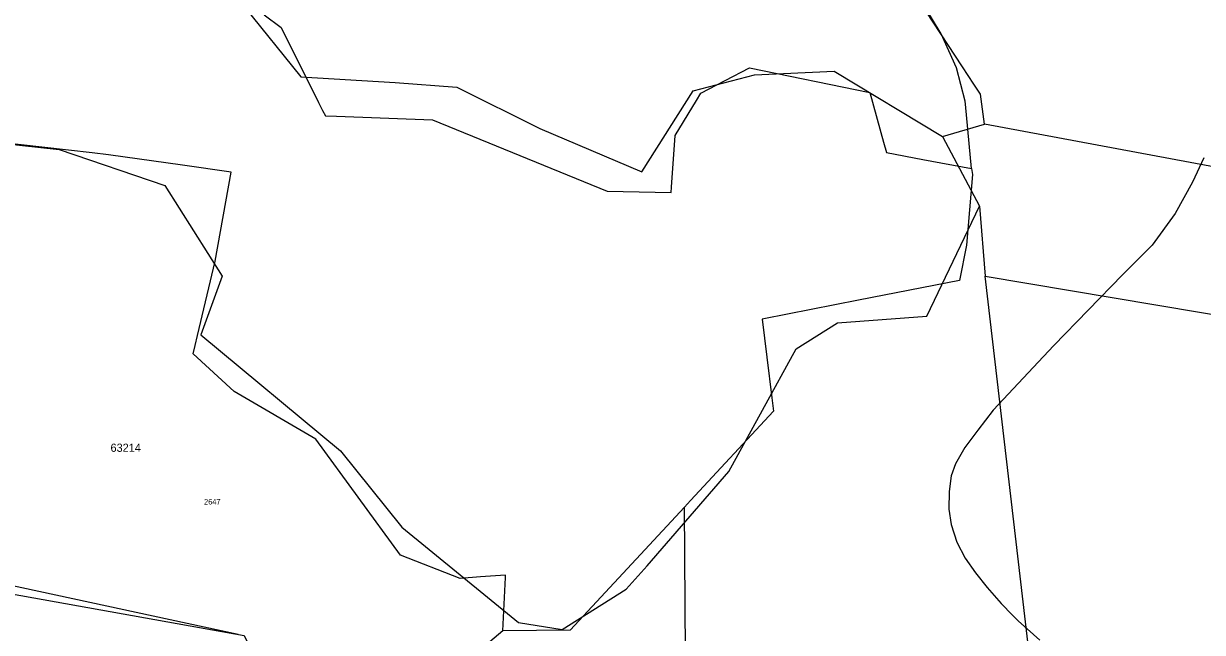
# Model space of a CAD drawing. Extents: x -546762 to -540209, y -1046851 to -1035694.
# Drawn here: x -542107.3 to -541745.8, y -1039679.2 to -1039492.4 of the extents above; entities that cross this region are included whole.
import ezdxf

# ---------------------------------------------------------------- set-up
doc = ezdxf.new("R2010")
doc.units = 0
for name, color, linetype in [('Vrstva 1', 7, 'Continuous'), ('Vrstva 18', 7, 'Continuous'), ('Vrstva 52', 7, 'Continuous'), ('Vrstva 53', 7, 'Continuous')]:
    doc.layers.add(name, color=color, linetype=linetype)

msp = doc.modelspace()

# ---------------------------------------------------------------- linework, layer by layer
at = {"layer": 'Vrstva 1'}
for points in [[(-542039.73, -1039487.11), (-542022.22, -1039508.76)], [(-541819.39, -1039505.7), (-541832.69, -1039485.45)], [(-541815.93, -1039510.98), (-541819.39, -1039505.7)], [(-542022.22, -1039508.76), (-541993.31, -1039510.56)], [(-541901.93, -1039513.05), (-541883.2, -1039508.2)], [(-541883.2, -1039508.2), (-541858.7, -1039506.99)], [(-541858.7, -1039506.99), (-541825.51, -1039527.09)], [(-541993.31, -1039510.56), (-541974.47, -1039511.93)], [(-541974.47, -1039511.93), (-541948.94, -1039524.67)], [(-541917.73, -1039537.91), (-541901.93, -1039513.05)], [(-541813.86, -1039514.13), (-541815.93, -1039510.98)], [(-541812.67, -1039523.33), (-541813.86, -1039514.13)], [(-542167.58, -1039523.29), (-542096.37, -1039531.1)], [(-541948.94, -1039524.67), (-541917.73, -1039537.91)], [(-541825.51, -1039527.09), (-541812.67, -1039523.33)], [(-541645.88, -1039554.4), (-541812.67, -1039523.33)], [(-541825.51, -1039527.09), (-541814.2, -1039548.41)], [(-542096.37, -1039531.1), (-542063.92, -1039542.07)], [(-542063.92, -1039542.07), (-542046.39, -1039569.86)], [(-541830.29, -1039582.16), (-541814.2, -1039548.41)], [(-541814.2, -1039548.41), (-541812.43, -1039569.86)], [(-542046.39, -1039569.86), (-542052.91, -1039587.93)], [(-541795.79, -1039712.66), (-541812.43, -1039569.86)], [(-541812.43, -1039569.86), (-541654.77, -1039596.43)], [(-541857.74, -1039584.21), (-541830.29, -1039582.16)], [(-541870.39, -1039592.22), (-541857.74, -1039584.21)], [(-542052.91, -1039587.93), (-542010.11, -1039623.43)], [(-541891.05, -1039629.78), (-541870.39, -1039592.22)], [(-542010.11, -1039623.43), (-541991.29, -1039646.92)], [(-541916.1, -1039658.75), (-541891.05, -1039629.78)], [(-541991.29, -1039646.92), (-541955.53, -1039676.11)], [(-541922.46, -1039665.92), (-541916.1, -1039658.75)], [(-542112.99, -1039664.24), (-542041.43, -1039679.65)], [(-541942.18, -1039678.24), (-541922.46, -1039665.92)], [(-541955.53, -1039676.11), (-541942.18, -1039678.24)]]:
    msp.add_lwpolyline(points, dxfattribs=at)
at = {"layer": 'Vrstva 52'}
for points in [[(-541816.57, -1039536.86), (-541818.49, -1039517.17), (-541818.58, -1039516.22), (-541821.19, -1039506.02), (-541825.9, -1039495.55), (-541831.54, -1039486.29)], [(-542033.52, -1039489.74), (-542028.29, -1039493.63), (-542016.8, -1039516.64), (-542015.57, -1039519.1), (-542014.75, -1039520.75), (-542011.28, -1039520.88), (-541981.89, -1039521.95), (-541928.3, -1039543.88), (-541908.7, -1039544.24), (-541908.59, -1039542.62), (-541907.49, -1039526.78), (-541900.97, -1039516.04), (-541899.59, -1039513.78), (-541884.67, -1039505.99), (-541847.8, -1039513.62), (-541843.6, -1039528.86), (-541842.73, -1039532.02), (-541831.56, -1039534.09), (-541816.57, -1039536.86)], [(-542055.23, -1039593.72), (-542054.62, -1039591.14), (-542053.91, -1039588.13), (-542048.51, -1039565.32), (-542043.67, -1039537.99), (-542058.56, -1039535.89), (-542081.23, -1039532.69), (-542086.22, -1039532.13), (-542129.93, -1039527.19)], [(-541745.4, -1039533.62), (-541748.83, -1039541.09), (-541754.21, -1039550.65), (-541761.23, -1039560.37), (-541770.34, -1039569.49), (-541791.4, -1039591.16), (-541794.56, -1039594.54), (-541809.96, -1039611.03), (-541814.65, -1039617.11), (-541818.68, -1039622.49), (-541821.52, -1039627.42), (-541822.86, -1039631.15), (-541823.46, -1039635.94), (-541823.61, -1039641.32), (-541822.86, -1039646.1), (-541821.07, -1039651.48), (-541818.53, -1039656.41), (-541815.39, -1039660.89), (-541811.81, -1039665.38), (-541807.48, -1039670.31), (-541804.05, -1039673.83), (-541802.25, -1039675.69), (-541799.58, -1039678.06), (-541795.68, -1039681.52)], [(-541816.57, -1039536.86), (-541816.29, -1039538.74), (-541818.2, -1039560.39), (-541820.33, -1039571.2), (-541851.23, -1039577.29), (-541880.31, -1039583.01), (-541880.84, -1039583.12), (-541879.4, -1039594.75), (-541877.86, -1039607.25), (-541877.36, -1039611.27), (-541902.76, -1039638.67), (-541904.65, -1039640.7)], [(-541960.29, -1039678.66), (-541959.51, -1039662.31), (-541959.48, -1039661.62), (-541967.16, -1039662.15), (-541973.42, -1039662.58), (-541991.74, -1039655.46), (-542017.62, -1039619.93), (-542042.66, -1039605.25), (-542055.23, -1039593.72)], [(-541904.65, -1039640.7), (-541926.23, -1039663.99), (-541939.68, -1039678.49), (-541960.29, -1039678.66)], [(-541895.16, -1039834.05), (-541906.66, -1039815.74), (-541914.31, -1039804.08), (-541917.9, -1039798.1), (-541921.04, -1039791.98), (-541923.13, -1039786.89), (-541924.32, -1039781.66), (-541924.61, -1039778.6), (-541924.92, -1039775.39), (-541924.97, -1039774.19), (-541925.22, -1039768.66), (-541924.32, -1039761.64), (-541921.93, -1039754.46), (-541917.9, -1039746.69), (-541913.27, -1039739.37), (-541909.09, -1039731.3), (-541907, -1039724.57), (-541905.35, -1039717.4), (-541904.56, -1039692.35), (-541904.34, -1039685.44), (-541904.65, -1039640.7)], [(-542117.97, -1039666.11), (-542039.62, -1039680.05), (-542020.59, -1039718.44), (-541996.59, -1039755.61)], [(-541960.29, -1039678.66), (-541966.97, -1039684.29), (-541971.12, -1039689.68), (-541975.48, -1039695.34), (-541981.01, -1039704.16), (-541984.89, -1039712.08), (-541988.18, -1039720.6), (-541990.72, -1039730.47), (-541994.01, -1039742.87), (-541996.59, -1039755.61)]]:
    msp.add_lwpolyline(points, dxfattribs=at)

# ---------------------------------------------------------------- texts
at = {"layer": 'Vrstva 18'}
msp.add_text('2647', height=1.7, dxfattribs=at).set_placement((-542051.94, -1039639.93))
at = {"layer": 'Vrstva 53'}
msp.add_text('63214', height=2.5, dxfattribs=at).set_placement((-542080.62, -1039623.77))

doc.saveas('drawing.dxf')
